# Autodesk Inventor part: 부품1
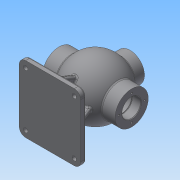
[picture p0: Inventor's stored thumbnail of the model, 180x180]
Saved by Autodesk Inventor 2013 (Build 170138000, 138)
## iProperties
Created: 2018-06
Part Number: 부품1
Material: 일반
Document SubType Name: Modeling
Designer: Administrator
Density: 1 g/cm^3
Author: Administrator
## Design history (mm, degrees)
sketch "스케치1"
  geometry: L1 (0, 53)-(0, -53); A1 r 53 centre (0, 0) between (0, -53) and (0, 53); 2 further points
  constraints: 2 coincident, 2 end point, 2 point on circle, 1 centre point, 1 midpoint, 1 vertical
  dimensions: "d1" = 106 diameter of A1
revolve "회전1" sketch "스케치1" stored, may be unused: angle "d2" = 90 deg
node "작업 평면1"
sketch "스케치2"
  geometry: C1 r 31 at (0, 0); 1 further point
  constraints: 1 centre point, 1 coincident
  dimensions: "d4" = 62 diameter of C1
extrude "돌출1" join sketch "스케치2" stored distance "d5" = 10; taper "d6" = 0 deg
sketch "스케치4"
  geometry: C1 r 31 at (0, 0) reference; C2 r 17.5 at (0, 0)
  constraints: 1 centre point, 1 coincident
  dimensions: "d7" = 35 diameter of C2
extrude "돌출2" cut sketch "스케치4" distance "d9" = 16; taper "d10" = 0 deg
sketch "스케치5"
  geometry: C1 r 17.5 at (0, 0) reference; C2 r 18.5 at (0, 0)
  constraints: 1 centre point, 1 coincident
  dimensions: "d12" = 37 diameter of C2
extrude "돌출3" cut sketch "스케치5" distance "d13" = 1.75; taper "d14" = 0 deg
node "작업 평면2"
sketch "스케치6"
  geometry: C1 r 31 at (0, 0); 1 further point
  constraints: 1 centre point, 1 coincident
  dimensions: "d16" = 62 diameter of C1
extrude "돌출4" join sketch "스케치6" stored distance "d17" = 62 (= d16); taper "d18" = 0 deg
sketch "스케치7"
  geometry: C1 r 31 at (0, 0) reference; C2 r 17.5 at (0, 0)
  constraints: 1 centre point, 1 coincident
  dimensions: "d19" = 35 diameter of C2
extrude "돌출5" cut sketch "스케치7" stored distance "d20" = 1.75; taper "d21" = 0 deg
node "작업 평면3"
sketch "스케치8"
  geometry: C1 r 27 at (0, 0); 1 further point
  constraints: 1 centre point, 1 coincident
  dimensions: "d23" = 54 diameter of C1
extrude "돌출6" join sketch "스케치8" stored distance "d24" = 1.75; taper "d25" = 0 deg
sketch "스케치9"
  geometry: C1 r 27 at (0, 0) reference; C2 r 13 at (0, 0)
  constraints: 1 centre point, 1 coincident
  dimensions: "d26" = 26 diameter of C2
sketch "스케치10"
  geometry: L1 (0, 43)-(0, -43); A1 r 43 centre (0, 0) between (0, -43) and (0, 43); 1 further point
  constraints: 2 end point, 2 point on circle, 1 centre point, 1 coincident, 1 midpoint, 1 vertical
  dimensions: "d27" = 86 diameter of A1
revolve "회전2" sketch "스케치10" stored, may be unused: angle "d28" = 90 deg
extrude "돌출7" cut sketch "스케치9" stored distance "d29" = 1.75; taper "d30" = 0 deg
node "작업 평면4"
sketch "스케치13"
  geometry: L1 (-57.5, 62.5)-(57.5, 62.5); L2 (57.5, 62.5)-(57.5, -62.5); L3 (57.5, -62.5)-(-57.5, -62.5); L4 (-57.5, -62.5)-(-57.5, 62.5); L5 (-57.5, 62.5)-(57.5, -62.5); L6 (57.5, 62.5)-(-57.5, -62.5); 1 further point
  constraints: 12 end point, 2 midpoint, 2 parallel, 1 horizontal, 1 perpendicular
  dimensions: "d36" = 115 distance of L2.end L3.end; "d37" = 125 distance of L1.end L2.end
extrude "돌출9" join sketch "스케치13" distance "d38" = 10; taper "d39" = 0 deg
sketch "스케치17"
  geometry: L1 (47.5, -4)-(-47.5, -4); L2 (-47.5, -4)-(-47.5, 4); L3 (-47.5, 4)-(47.5, 4); L4 (47.5, 4)-(47.5, -4); L5 (47.5, -4)-(-47.5, 4); L6 (-47.5, -4)-(47.5, 4); 1 further point
  constraints: 12 end point, 2 midpoint, 2 parallel, 1 horizontal, 1 perpendicular
  dimensions: "d46" = 95 distance of L2.end L3.end; "d47" = 8 distance of L1.end L2.end
extrude "돌출10" join sketch "스케치17" stored distance "d48" = 10; taper "d49" = 0 deg
sketch "스케치18"
  geometry: L1 (-75, 52.5)-(-43.9, 39.935); L2 (-85, 62.5)-(-75, 62.5) reference; L3 (-75, -62.5)-(-75, 62.5) reference; 1 further point
  constraints: 2 end point, 1 point on line
  dimensions: "d50" = 10 distance from line of L2 L1.start; "d51" = 22 deg angle of L1 L2
feature "리브1" sketch "스케치18" dims "d52" = 1, "d53" = 8, "d54" = 0, "d55" = 0, "d56" = 1, "d57" = 1
feature "면 기울기1" dims angle "d58" = 22 deg
fillet "모깎기1" dims "d59" = 12
sketch "스케치21"
  geometry: A1 r 12 centre (-45.5, 50.5) between (-45.5, 62.5) and (-57.5, 50.5) reference; 2 further points
  constraints: 1 coincident
hole "구멍1" sketch "스케치21" at (-45.5, 50.5) diameter "d60" = 8; stored, may be unused: countersink angle "d64" = 90 deg, drill point angle "d66" = 118 deg; dims "d61" = 6, "d62" = 12, "d63" = 3, "d65" = 8
fillet "모깎기2" dims "d67" = 3
fillet "모깎기3" dims "d68" = 3
fillet "모깎기4" dims "d69" = 3
fillet "모깎기5" dims "d70" = 3
chamfer "모따기1" distance "d71" = 1; stored, may be unused: second distance "d72" = 2, angle "d73" = 45 deg
node "작업 평면5"
sketch "스케치22"
  geometry: C1 r 18.5 at (0, 0); 1 further point
  constraints: 1 centre point, 1 coincident
  dimensions: "d75" = 37 diameter of C1
extrude "돌출11" cut sketch "스케치22" distance "d76" = 1.75; taper "d77" = 0 deg
sketch "스케치23"
  geometry: C1 r 27 at (0, 0) reference; 1 further point
  constraints: 1 vertical alignment
  dimensions: "d78" = 20 distance of C1.centre point (0, 20)
hole "구멍2" sketch "스케치23" at (0, 20) diameter "d79" = 3.242; stored, may be unused: countersink angle "d83" = 90 deg, drill point angle "d85" = 118 deg; dims "d80" = 9, "d81" = 4, "d82" = 2, "d84" = 11
sketch "스케치24"
  geometry: C1 r 31 at (0, 0) reference; 1 further point
  constraints: 1 vertical alignment
  dimensions: "d89" = 24 distance of C1.centre point (0, 24)
hole "구멍3" sketch "스케치24" at (0, 24) diameter "d90" = 3.242; stored, may be unused: countersink angle "d94" = 90 deg, drill point angle "d96" = 118 deg; dims "d91" = 16, "d92" = 4, "d93" = 2, "d95" = 19
sketch "스케치25"
  geometry: C1 r 31 at (0, 0) reference; 1 further point
  constraints: 1 vertical alignment
  dimensions: "d100" = 22.5 distance of C1.centre point (0, 22.5)
hole "구멍4" sketch "스케치25" at (0, 22.5) diameter "d101" = 3.242; stored, may be unused: countersink angle "d105" = 90 deg, drill point angle "d107" = 118 deg; dims "d102" = 12, "d103" = 4, "d104" = 2, "d106" = 15
node "작업 평면6"
sketch "스케치26"
  geometry: L1 (-27, 65)-(27, 65) reference; L2 (-27, 47.286)-(27, 47.286) reference; L3 (-27, 65)-(-27, 47.286) reference; 2 further points
  constraints: 1 other
  dimensions: "d112" = 27 distance from line of L3 point (0, 55); "d113" = 10 distance from line of L1 point (0, 55)
feature "엠보싱1" sketch "스케치26" dims "d114" = 0.5, "d115" = 0
node "솔리드1"
mirror "대칭1"
mirror "대칭2"
mirror "대칭3"
pattern_circular "원형 패턴1" dims angle "d87" = 360 deg
pattern_circular "원형 패턴2" dims angle "d98" = 360 deg
pattern_circular "원형 패턴3" dims angle "d109" = 360 deg
node "투영된 루프2"
other parameters: "d3" = 68, "d15" = -68, "d22" = 65, "d74" = -16, "d111" = -27
